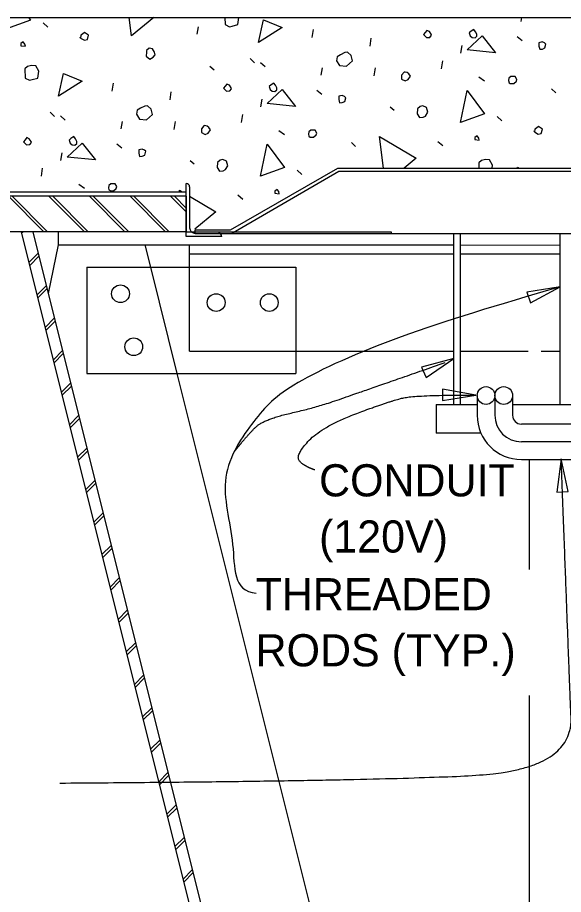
# Model space of a CAD drawing. Extents: x 927736.2 to 927809.6, y 636703.6 to 636757.7.
# Drawn here: x 927758.39 to 927764.73, y 636721.33 to 636731.52 of the extents above; entities that cross this region are included whole.
import ezdxf

# ---------------------------------------------------------------- set-up
doc = ezdxf.new("R2010")
doc.units = 0
for name, color, linetype in [('Default', 7, 'Continuous'), ('DimLines_dp', 7, 'Continuous'), ('Miscellaneous1', 7, 'Continuous'), ('Miscellaneous2', 7, 'Continuous'), ('Miscellaneous3', 7, 'Continuous')]:
    doc.layers.add(name, color=color, linetype=linetype)

msp = doc.modelspace()

# ---------------------------------------------------------------- linework, layer by layer
at = {"layer": 'Default'}
msp.add_line((927758.438, 636729.014), (927758.453, 636729.029), dxfattribs=at)
at = {"layer": 'DimLines_dp'}
for points in [[(927764.692, 636728.389), (927764.306, 636728.326), (927764.349, 636728.202)], [(927763.458, 636727.557), (927763.081, 636727.455), (927763.135, 636727.336)], [(927763.711, 636727.133), (927763.325, 636727.199), (927763.325, 636727.068)], [(927764.705, 636726.393), (927764.654, 636726.006), (927764.785, 636726.011)]]:
    msp.add_lwpolyline(points, close=True, dxfattribs=at)
for points, degree in [([(927764.692, 636728.389), (927763.962, 636728.176), (927762.754, 636727.81), (927761.495, 636727.244), (927761.155, 636726.878), (927760.689, 636726.198), (927760.946, 636725.403), (927760.886, 636724.856), (927761.163, 636724.831)], 3), ([(927760.903, 636726.468), (927761.067, 636726.677), (927761.256, 636726.853), (927761.873, 636726.992), (927762.515, 636727.218), (927763.355, 636727.509)], 2), ([(927761.841, 636726.264), (927761.696, 636726.315), (927761.621, 636726.441), (927761.929, 636726.768), (927762.729, 636727.07), (927763.037, 636727.133), (927763.711, 636727.133)], 2), ([(927758.883, 636722.628), (927762.516, 636722.653), (927764.844, 636722.779), (927764.793, 636724), (927764.705, 636726.393)], 2)]:
    msp.add_open_spline(points, degree=degree, dxfattribs=at)
at = {"layer": 'Miscellaneous1'}
for p, q in [((927763.728, 636727.127), (927763.728, 636726.898)), ((927763.934, 636727.127), (927763.934, 636726.898)), ((927764.139, 636727.127), (927764.139, 636726.898)), ((927763.253, 636727.024), (927763.253, 636726.69)), ((927763.253, 636727.024), (927763.728, 636727.024)), ((927764.139, 636727.024), (927764.974, 636727.024)), ((927765.656, 636726.795), (927764.242, 636726.795)), ((927763.772, 636726.69), (927763.253, 636726.69)), ((927765.66, 636726.589), (927764.242, 636726.59)), ((927764.242, 636726.384), (927765.662, 636726.383))]:
    msp.add_line(p, q, dxfattribs=at)
for centre in [(927763.831, 636727.127), (927764.037, 636727.127)]:
    msp.add_circle(centre, 0.103, dxfattribs=at)
for radius in [0.514, 0.308, 0.103]:
    msp.add_arc((927764.242, 636726.898), radius, 180, 269.9792, dxfattribs=at)
at = {"layer": 'Miscellaneous2'}
for p, q in [((927753.063, 636731.515), (927774, 636731.515)), ((927764.24, 636731.468), (927764.248, 636731.515)), ((927758.689, 636731.455), (927758.741, 636731.405)), ((927760.475, 636731.321), (927760.49, 636731.408)), ((927761.813, 636731.283), (927761.826, 636731.376)), ((927762.485, 636731.183), (927762.498, 636731.275)), ((927764.191, 636731.295), (927764.249, 636731.247)), ((927763.54, 636731.102), (927763.555, 636731.189)), ((927761.093, 636731.039), (927761.144, 636730.989)), ((927763.315, 636730.92), (927763.328, 636731.013)), ((927760.625, 636730.952), (927760.675, 636730.908)), ((927761.213, 636730.995), (927761.265, 636730.945)), ((927761.917, 636730.845), (927761.932, 636730.932)), ((927762.532, 636730.838), (927762.546, 636730.931)), ((927763.749, 636730.825), (927763.812, 636730.779)), ((927759.49, 636730.661), (927759.503, 636730.754)), ((927760.161, 636730.56), (927760.175, 636730.653)), ((927761.868, 636730.673), (927761.925, 636730.624)), ((927764.59, 636730.687), (927764.64, 636730.643)), ((927761.217, 636730.479), (927761.232, 636730.566)), ((927758.77, 636730.417), (927758.821, 636730.367)), ((927760.992, 636730.297), (927761.005, 636730.39)), ((927762.718, 636730.479), (927762.766, 636730.441)), ((927758.89, 636730.373), (927758.942, 636730.323)), ((927759.594, 636730.223), (927759.609, 636730.31)), ((927760.209, 636730.215), (927760.223, 636730.308)), ((927763.961, 636730.365), (927764.013, 636730.315)), ((927761.425, 636730.203), (927761.489, 636730.156)), ((927759.545, 636730.05), (927759.602, 636730.002)), ((927762.267, 636730.064), (927762.317, 636730.02)), ((927763.272, 636730.078), (927763.33, 636730.03)), ((927758.894, 636729.857), (927758.909, 636729.944)), ((927760.395, 636729.856), (927760.443, 636729.818)), ((927758.669, 636729.675), (927758.682, 636729.768)), ((927760.864, 636729.049), (927762.11, 636729.768)), ((927760.874, 636729.01), (927762.121, 636729.73)), ((927761.638, 636729.743), (927761.69, 636729.693)), ((927762.11, 636729.768), (927774, 636729.768)), ((927762.121, 636729.73), (927774, 636729.73)), ((927759.102, 636729.58), (927759.166, 636729.534)), ((927760.35, 636728.972), (927760.35, 636729.588)), ((927756.631, 636729.491), (927760.35, 636729.491)), ((927760.389, 636729.55), (927760.389, 636729.074)), ((927758.696, 636729.029), (927758.284, 636729.44)), ((927758.739, 636729.029), (927758.328, 636729.44)), ((927759.167, 636729.029), (927758.755, 636729.44)), ((927759.21, 636729.029), (927758.799, 636729.44)), ((927759.638, 636729.029), (927759.226, 636729.44)), ((927759.681, 636729.029), (927759.27, 636729.44)), ((927760.108, 636729.029), (927759.697, 636729.44)), ((927760.152, 636729.029), (927759.741, 636729.44)), ((927760.35, 636729.258), (927760.168, 636729.44)), ((927760.35, 636729.302), (927760.212, 636729.44)), ((927760.35, 636729.44), (927760.35, 636729.029)), ((927760.949, 636729.456), (927761.007, 636729.408)), ((927760.344, 636729.029), (927760.35, 636729.035)), ((927760.344, 636729.029), (927760.35, 636729.035)), ((927760.761, 636728.972), (927760.35, 636728.972)), ((927760.453, 636729.049), (927760.864, 636729.049)), ((927760.453, 636729.01), (927760.453, 636729.049)), ((927760.453, 636729.01), (927760.723, 636729.01)), ((927760.453, 636729.01), (927774, 636729.01))]:
    msp.add_line(p, q, dxfattribs=at)
for points in [[(927758.519, 636731.515), (927758.541, 636731.486), (927758.261, 636731.385)], [(927759.714, 636731.302), (927759.687, 636731.515)], [(927759.972, 636731.515), (927759.714, 636731.302)], [(927760.799, 636731.515), (927760.802, 636731.434), (927760.853, 636731.409), (927760.883, 636731.417), (927760.949, 636731.435), (927760.959, 636731.514), (927760.959, 636731.515)], [(927761.19, 636731.225), (927761.247, 636731.489), (927761.462, 636731.4), (927761.19, 636731.225)], [(927759.12, 636731.277), (927759.166, 636731.251), (927759.201, 636731.26), (927759.214, 636731.309), (927759.167, 636731.341), (927759.146, 636731.322), (927759.124, 636731.31), (927759.12, 636731.277), (927759.117, 636731.289)], [(927763.106, 636731.317), (927763.141, 636731.282), (927763.178, 636731.285), (927763.197, 636731.31), (927763.194, 636731.322), (927763.173, 636731.354), (927763.144, 636731.366), (927763.125, 636731.341), (927763.106, 636731.317)], [(927763.613, 636731.14), (927763.787, 636731.302), (927763.941, 636731.107), (927763.613, 636731.14)], [(927763.646, 636731.302), (927763.671, 636731.283), (927763.703, 636731.279), (927763.724, 636731.298), (927763.724, 636731.323), (927763.71, 636731.351), (927763.69, 636731.378), (927763.657, 636731.356), (927763.637, 636731.338), (927763.646, 636731.302)], [(927758.429, 636731.188), (927758.482, 636731.183), (927758.475, 636731.206), (927758.455, 636731.233), (927758.429, 636731.213), (927758.429, 636731.188)], [(927764.444, 636731.184), (927764.454, 636731.148), (927764.485, 636731.15), (927764.513, 636731.164), (927764.527, 636731.206), (927764.511, 636731.221), (927764.482, 636731.233), (927764.446, 636731.223), (927764.444, 636731.184)], [(927759.886, 636731.112), (927759.885, 636731.067), (927759.926, 636731.033), (927759.965, 636731.056), (927759.99, 636731.082), (927759.982, 636731.112), (927759.959, 636731.151), (927759.918, 636731.159), (927759.887, 636731.131), (927759.886, 636731.112)], [(927762.095, 636731.014), (927762.129, 636730.96), (927762.209, 636730.949), (927762.281, 636731.013), (927762.265, 636731.073), (927762.222, 636731.112), (927762.191, 636731.11), (927762.141, 636731.084), (927762.102, 636731.061), (927762.095, 636731.014)], [(927758.476, 636730.919), (927758.479, 636730.811), (927758.53, 636730.787), (927758.56, 636730.795), (927758.625, 636730.812), (927758.636, 636730.892), (927758.601, 636730.953), (927758.554, 636730.959), (927758.507, 636730.947), (927758.476, 636730.919)], [(927758.867, 636730.603), (927758.924, 636730.867), (927759.139, 636730.778), (927758.867, 636730.603)], [(927762.849, 636730.846), (927762.848, 636730.801), (927762.892, 636730.781), (927762.926, 636730.797), (927762.954, 636730.836), (927762.934, 636730.862), (927762.917, 636730.877), (927762.89, 636730.883), (927762.879, 636730.88), (927762.849, 636730.846)], [(927764.098, 636730.759), (927764.113, 636730.751), (927764.152, 636730.748), (927764.183, 636730.776), (927764.19, 636730.797), (927764.169, 636730.829), (927764.118, 636730.829), (927764.097, 636730.81), (927764.092, 636730.783), (927764.098, 636730.759)], [(927760.783, 636730.695), (927760.818, 636730.659), (927760.855, 636730.663), (927760.874, 636730.687), (927760.871, 636730.699), (927760.85, 636730.732), (927760.821, 636730.743), (927760.802, 636730.719), (927760.783, 636730.695)], [(927761.323, 636730.68), (927761.347, 636730.661), (927761.38, 636730.657), (927761.401, 636730.675), (927761.401, 636730.701), (927761.387, 636730.729), (927761.367, 636730.755), (927761.334, 636730.734), (927761.314, 636730.716), (927761.323, 636730.68)], [(927761.29, 636730.518), (927761.464, 636730.679), (927761.618, 636730.484), (927761.29, 636730.518)], [(927762.121, 636730.562), (927762.131, 636730.526), (927762.162, 636730.528), (927762.19, 636730.542), (927762.204, 636730.584), (927762.188, 636730.599), (927762.159, 636730.61), (927762.123, 636730.601), (927762.121, 636730.562)], [(927763.533, 636730.295), (927763.612, 636730.667), (927763.813, 636730.396), (927763.533, 636730.295)], [(927759.772, 636730.392), (927759.806, 636730.337), (927759.886, 636730.327), (927759.958, 636730.391), (927759.942, 636730.45), (927759.899, 636730.49), (927759.868, 636730.488), (927759.818, 636730.462), (927759.779, 636730.438), (927759.772, 636730.392)], [(927763.037, 636730.456), (927763.033, 636730.397), (927763.058, 636730.353), (927763.101, 636730.358), (927763.129, 636730.372), (927763.156, 636730.417), (927763.141, 636730.471), (927763.097, 636730.491), (927763.068, 636730.483), (927763.037, 636730.456)], [(927760.526, 636730.224), (927760.525, 636730.179), (927760.569, 636730.159), (927760.603, 636730.174), (927760.631, 636730.213), (927760.611, 636730.24), (927760.594, 636730.255), (927760.567, 636730.26), (927760.555, 636730.257), (927760.526, 636730.224)], [(927761.775, 636730.137), (927761.79, 636730.128), (927761.829, 636730.126), (927761.86, 636730.153), (927761.867, 636730.174), (927761.846, 636730.207), (927761.795, 636730.206), (927761.774, 636730.188), (927761.769, 636730.161), (927761.775, 636730.137)], [(927764.392, 636730.187), (927764.437, 636730.161), (927764.473, 636730.17), (927764.486, 636730.218), (927764.439, 636730.251), (927764.418, 636730.232), (927764.396, 636730.22), (927764.392, 636730.187), (927764.389, 636730.199)], [(927758.46, 636730.072), (927758.495, 636730.037), (927758.532, 636730.041), (927758.551, 636730.065), (927758.548, 636730.077), (927758.527, 636730.109), (927758.498, 636730.121), (927758.479, 636730.096), (927758.46, 636730.072)], [(927759, 636730.057), (927759.024, 636730.038), (927759.057, 636730.034), (927759.078, 636730.053), (927759.078, 636730.078), (927759.064, 636730.106), (927759.044, 636730.133), (927759.011, 636730.111), (927758.991, 636730.093), (927759, 636730.057)], [(927762.64, 636729.768), (927762.593, 636730.133), (927763.018, 636729.883), (927762.879, 636729.768)], [(927763.701, 636730.098), (927763.753, 636730.092), (927763.747, 636730.116), (927763.727, 636730.143), (927763.701, 636730.123), (927763.701, 636730.098)], [(927758.967, 636729.895), (927759.141, 636730.057), (927759.295, 636729.862), (927758.967, 636729.895)], [(927759.798, 636729.939), (927759.808, 636729.903), (927759.839, 636729.905), (927759.867, 636729.919), (927759.881, 636729.962), (927759.865, 636729.976), (927759.836, 636729.988), (927759.8, 636729.978), (927759.798, 636729.939)], [(927761.21, 636729.673), (927761.289, 636730.045), (927761.49, 636729.773), (927761.21, 636729.673)], [(927760.714, 636729.833), (927760.71, 636729.775), (927760.735, 636729.731), (927760.778, 636729.736), (927760.806, 636729.75), (927760.833, 636729.795), (927760.818, 636729.849), (927760.774, 636729.869), (927760.745, 636729.861), (927760.714, 636729.833)], [(927763.903, 636729.768), (927763.908, 636729.802), (927763.872, 636729.863), (927763.826, 636729.869), (927763.778, 636729.857), (927763.747, 636729.829)], [(927763.747, 636729.829), (927763.749, 636729.768)], [(927764.194, 636729.768), (927764.195, 636729.777), (927764.216, 636729.768)], [(927759.452, 636729.515), (927759.467, 636729.506), (927759.506, 636729.503), (927759.537, 636729.531), (927759.544, 636729.552), (927759.523, 636729.584), (927759.472, 636729.584), (927759.451, 636729.565), (927759.446, 636729.538), (927759.452, 636729.515)], [(927760.273, 636729.491), (927760.27, 636729.51), (927760.303, 636729.491)], [(927761.378, 636729.475), (927761.43, 636729.47), (927761.424, 636729.494), (927761.404, 636729.52), (927761.377, 636729.501), (927761.378, 636729.475)], [(927760.389, 636729.441), (927760.695, 636729.26), (927760.451, 636729.059)]]:
    msp.add_lwpolyline(points, dxfattribs=at)
for centre, radius, start, end in [((927760.35, 636729.55), 0.0385, 359.9953, 89.9953), ((927760.453, 636729.074), 0.0642, 179.9953, 269.9953), ((927760.723, 636728.972), 0.0385, 359.9953, 89.9953)]:
    msp.add_arc(centre, radius, start, end, dxfattribs=at)
at = {"layer": 'Miscellaneous3'}
for p, q in [((927760.35, 636729.44), (927756.65, 636729.44)), ((927760.35, 636729.029), (927756.65, 636729.029)), ((927758.434, 636729.029), (927762.288, 636713.612)), ((927758.566, 636729.029), (927762.42, 636713.612)), ((927758.867, 636728.875), (927758.867, 636729.029)), ((927760.35, 636729.029), (927762.729, 636729.029)), ((927762.729, 636729.029), (927762.729, 636729.01)), ((927763.458, 636727.024), (927763.458, 636729.01)), ((927763.535, 636727.024), (927763.535, 636729.01)), ((927764.692, 636727.024), (927764.692, 636729.01)), ((927758.862, 636728.875), (927758.745, 636728.313)), ((927758.867, 636728.875), (927763.458, 636728.875)), ((927759.868, 636728.875), (927759.933, 636728.618)), ((927760.389, 636728.592), (927760.389, 636728.875)), ((927763.535, 636728.875), (927764.692, 636728.874)), ((927758.523, 636728.672), (927758.629, 636728.778)), ((927760.389, 636727.641), (927760.389, 636728.772)), ((927760.389, 636728.772), (927763.458, 636728.772)), ((927763.535, 636728.772), (927764.692, 636728.772)), ((927758.532, 636728.637), (927758.638, 636728.743)), ((927759.194, 636728.618), (927759.194, 636727.384)), ((927759.194, 636728.618), (927761.622, 636728.618)), ((927759.933, 636728.618), (927760.241, 636727.384)), ((927761.622, 636728.618), (927761.622, 636727.384)), ((927758.617, 636728.295), (927758.723, 636728.401)), ((927758.626, 636728.26), (927758.732, 636728.366)), ((927758.711, 636727.918), (927758.817, 636728.024)), ((927758.72, 636727.883), (927758.826, 636727.989)), ((927758.806, 636727.542), (927758.912, 636727.648)), ((927760.389, 636727.641), (927761.622, 636727.641)), ((927761.622, 636727.641), (927763.458, 636727.641)), ((927763.535, 636727.641), (927764.319, 636727.641)), ((927764.473, 636727.641), (927764.692, 636727.641)), ((927758.814, 636727.507), (927758.92, 636727.613)), ((927759.194, 636727.384), (927761.622, 636727.384)), ((927760.241, 636727.384), (927762.676, 636717.646)), ((927758.9, 636727.165), (927759.006, 636727.271)), ((927758.909, 636727.13), (927759.015, 636727.236)), ((927758.994, 636726.788), (927759.1, 636726.894)), ((927759.003, 636726.753), (927759.109, 636726.859)), ((927759.088, 636726.411), (927759.194, 636726.517)), ((927759.097, 636726.376), (927759.203, 636726.482)), ((927759.182, 636726.035), (927759.288, 636726.141)), ((927759.191, 636726), (927759.297, 636726.106)), ((927759.277, 636725.658), (927759.383, 636725.764)), ((927759.285, 636725.623), (927759.391, 636725.729)), ((927759.371, 636725.281), (927759.477, 636725.387)), ((927759.379, 636725.246), (927759.485, 636725.352)), ((927759.465, 636724.904), (927759.571, 636725.01)), ((927759.474, 636724.869), (927759.58, 636724.975)), ((927759.559, 636724.528), (927759.665, 636724.634)), ((927759.568, 636724.493), (927759.674, 636724.599)), ((927759.653, 636724.151), (927759.759, 636724.257)), ((927759.662, 636724.116), (927759.768, 636724.222)), ((927759.748, 636723.774), (927759.853, 636723.88)), ((927759.756, 636723.739), (927759.862, 636723.845)), ((927759.842, 636723.397), (927759.948, 636723.503)), ((927759.85, 636723.362), (927759.956, 636723.468)), ((927759.936, 636723.021), (927760.042, 636723.127)), ((927759.945, 636722.986), (927760.051, 636723.092)), ((927760.03, 636722.644), (927760.136, 636722.75)), ((927760.039, 636722.609), (927760.145, 636722.715)), ((927760.124, 636722.267), (927760.23, 636722.373)), ((927760.133, 636722.232), (927760.239, 636722.338)), ((927760.218, 636721.89), (927760.324, 636721.996)), ((927760.227, 636721.856), (927760.333, 636721.961)), ((927760.313, 636721.514), (927760.419, 636721.62)), ((927760.321, 636721.479), (927760.427, 636721.585))]:
    msp.add_line(p, q, dxfattribs=at)
for points in [[(927764.332, 636726.384), (927764.332, 636725.108)], [(927764.332, 636723.646), (927764.332, 636718.446), (927768.032, 636718.446)]]:
    msp.add_lwpolyline(points, dxfattribs=at)
for centre in [(927759.586, 636728.309), (927760.697, 636728.206), (927761.314, 636728.206), (927759.74, 636727.693)]:
    msp.add_circle(centre, 0.103, dxfattribs=at)

# ---------------------------------------------------------------- texts
at = {"layer": 'DimLines_dp'}
for s, height, p in [('CONDUIT', 0.373, (927761.892, 636725.956)), ('(120V)', 0.373, (927761.892, 636725.304)), ('THREADED', 0.373, (927761.155, 636724.634)), ('RODS (TYP.)', 0.37296, (927761.155, 636723.983))]:
    msp.add_text(s, height=height, dxfattribs=at).set_placement(p)

doc.saveas('drawing.dxf')
